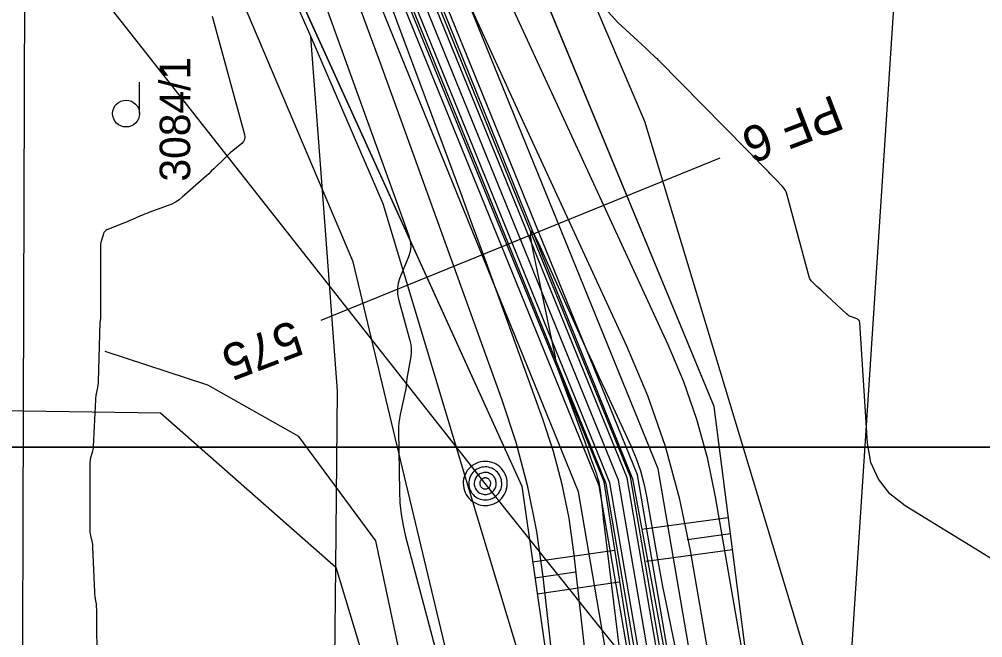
# Model space of a CAD drawing. Extents: x -534410 to -534262, y -1190162 to -1189584.
# Drawn here: x -534342.11 to -534315.26, y -1190009.78 to -1189992.54 of the extents above; entities that cross this region are included whole.
import ezdxf

# ---------------------------------------------------------------- set-up
doc = ezdxf.new("R2010")
doc.units = 0
for name, color, linetype in [('07_ELEKTRO', 7, 'Continuous'), ('30', 7, 'Continuous'), ('31', 7, 'Continuous'), ('_linie', 7, 'Continuous'), ('_N_osa', 7, 'Continuous'), ('_N_tenká', 7, 'Continuous'), ('_N_tenká_velmi', 7, 'Continuous'), ('_N_text', 7, 'Continuous'), ('_přístup', 7, 'Continuous'), ('_rámeček', 7, 'Continuous'), ('_tenka', 7, 'Continuous'), ('_velmi_tenka', 7, 'Continuous'), ('Default', 7, 'Continuous'), ('Hranice parcel', 7, 'Continuous'), ('Parcelní čísla', 7, 'Continuous'), ('Vrstva 12', 7, 'Continuous'), ('Vrstva 15', 7, 'Continuous'), ('Vrstva 2', 7, 'Continuous'), ('Značky kultur', 7, 'Continuous')]:
    doc.layers.add(name, color=color, linetype=linetype)

# ---------------------------------------------------------------- blocks, each defined once
blk = doc.blocks.new('VN460')
at = {"layer": 'Vrstva 2'}
for points in [[(0.1229, -0.0001), (0.1221, 0.0128), (0.1201, 0.0255), (0.1168, 0.0379), (0.1122, 0.0499), (0.1064, 0.0613), (0.0994, 0.0722), (0.0913, 0.0822), (0.0822, 0.0912), (0.0722, 0.0993), (0.0614, 0.1063), (0.05, 0.1122), (0.0379, 0.1168), (0.0256, 0.1201), (0.0128, 0.1221), (0, 0.1228), (-0.0128, 0.1221), (-0.0256, 0.1201), (-0.0379, 0.1168), (-0.05, 0.1122), (-0.0614, 0.1063), (-0.0722, 0.0993), (-0.0822, 0.0912), (-0.0913, 0.0822), (-0.0994, 0.0722), (-0.1064, 0.0613), (-0.1122, 0.0499), (-0.1168, 0.0379), (-0.1202, 0.0255), (-0.1221, 0.0128), (-0.1229, -0.0001), (-0.1221, -0.0129), (-0.1202, -0.0256), (-0.1168, -0.038), (-0.1122, -0.05), (-0.1064, -0.0615), (-0.0994, -0.0723), (-0.0913, -0.0823), (-0.0822, -0.0914), (-0.0722, -0.0995), (-0.0614, -0.1064), (-0.05, -0.1123), (-0.0379, -0.1169), (-0.0256, -0.1202), (-0.0128, -0.1223), (0, -0.1229), (0.0128, -0.1222), (0.0256, -0.1202), (0.0379, -0.1169), (0.05, -0.1123), (0.0614, -0.1064), (0.0722, -0.0995), (0.0822, -0.0914), (0.0913, -0.0823), (0.0994, -0.0723), (0.1064, -0.0615), (0.1122, -0.05), (0.1168, -0.038), (0.1201, -0.0256), (0.1221, -0.0129), (0.1229, -0.0001)], [(0.0922, -0.0001), (0.0916, 0.0096), (0.0901, 0.0191), (0.0876, 0.0284), (0.0842, 0.0374), (0.0798, 0.046), (0.0745, 0.0541), (0.0685, 0.0616), (0.0616, 0.0684), (0.0541, 0.0745), (0.046, 0.0797), (0.0375, 0.0841), (0.0285, 0.0876), (0.0191, 0.0901), (0.0096, 0.0916), (0, 0.0921), (-0.0096, 0.0916), (-0.0191, 0.0901), (-0.0285, 0.0876), (-0.0375, 0.0841), (-0.0461, 0.0797), (-0.0542, 0.0745), (-0.0617, 0.0684), (-0.0685, 0.0616), (-0.0745, 0.0541), (-0.0798, 0.046), (-0.0842, 0.0374), (-0.0876, 0.0284), (-0.0901, 0.0191), (-0.0916, 0.0096), (-0.0921, -0.0001), (-0.0916, -0.0097), (-0.0901, -0.0192), (-0.0876, -0.0285), (-0.0842, -0.0375), (-0.0798, -0.0461), (-0.0745, -0.0542), (-0.0685, -0.0617), (-0.0616, -0.0685), (-0.0542, -0.0746), (-0.0461, -0.0798), (-0.0375, -0.0842), (-0.0285, -0.0877), (-0.0191, -0.0902), (-0.0096, -0.0917), (0, -0.0922), (0.0096, -0.0917), (0.0191, -0.0902), (0.0285, -0.0877), (0.0375, -0.0842), (0.046, -0.0798), (0.0541, -0.0746), (0.0616, -0.0685), (0.0685, -0.0617), (0.0745, -0.0542), (0.0798, -0.0461), (0.0842, -0.0375), (0.0876, -0.0285), (0.0901, -0.0192), (0.0916, -0.0097), (0.0922, -0.0001)], [(0.0614, -0.0001), (0.0611, 0.0063), (0.0601, 0.0127), (0.0584, 0.0189), (0.0561, 0.0249), (0.0532, 0.0306), (0.0497, 0.036), (0.0456, 0.041), (0.0411, 0.0456), (0.0361, 0.0496), (0.0307, 0.0531), (0.025, 0.056), (0.019, 0.0584), (0.0128, 0.06), (0.0064, 0.061), (0, 0.0613), (-0.0064, 0.061), (-0.0128, 0.06), (-0.019, 0.0584), (-0.025, 0.056), (-0.0307, 0.0531), (-0.0361, 0.0496), (-0.0411, 0.0456), (-0.0457, 0.041), (-0.0497, 0.036), (-0.0532, 0.0306), (-0.0561, 0.0249), (-0.0584, 0.0189), (-0.0601, 0.0127), (-0.0611, 0.0063), (-0.0614, -0.0001), (-0.0611, -0.0065), (-0.0601, -0.0128), (-0.0584, -0.0191), (-0.0561, -0.025), (-0.0532, -0.0308), (-0.0497, -0.0361), (-0.0457, -0.0411), (-0.0411, -0.0457), (-0.0361, -0.0498), (-0.0307, -0.0532), (-0.025, -0.0561), (-0.019, -0.0585), (-0.0128, -0.0601), (-0.0064, -0.0611), (0, -0.0615), (0.0064, -0.0611), (0.0128, -0.0601), (0.019, -0.0585), (0.025, -0.0561), (0.0307, -0.0532), (0.0361, -0.0498), (0.0411, -0.0457), (0.0456, -0.0411), (0.0497, -0.0361), (0.0532, -0.0308), (0.0561, -0.025), (0.0584, -0.0191), (0.0601, -0.0128), (0.0611, -0.0065), (0.0614, -0.0001)], [(0.0307, -0.0001), (0.0306, 0.0031), (0.03, 0.0063), (0.0292, 0.0094), (0.0281, 0.0124), (0.0266, 0.0153), (0.0248, 0.018), (0.0228, 0.0205), (0.0206, 0.0228), (0.0181, 0.0248), (0.0153, 0.0265), (0.0125, 0.028), (0.0095, 0.0291), (0.0064, 0.03), (0.0032, 0.0305), (0, 0.0306), (-0.0032, 0.0305), (-0.0064, 0.03), (-0.0095, 0.0291), (-0.0125, 0.028), (-0.0154, 0.0265), (-0.0181, 0.0248), (-0.0206, 0.0228), (-0.0228, 0.0205), (-0.0248, 0.018), (-0.0266, 0.0153), (-0.0281, 0.0124), (-0.0292, 0.0094), (-0.03, 0.0063), (-0.0306, 0.0031), (-0.0307, -0.0001), (-0.0306, -0.0033), (-0.03, -0.0065), (-0.0292, -0.0095), (-0.0281, -0.0126), (-0.0266, -0.0154), (-0.0248, -0.0181), (-0.0228, -0.0206), (-0.0206, -0.0229), (-0.0181, -0.0249), (-0.0154, -0.0267), (-0.0125, -0.0281), (-0.0095, -0.0292), (-0.0064, -0.0301), (-0.0032, -0.0306), (0, -0.0308), (0.0032, -0.0306), (0.0064, -0.0301), (0.0095, -0.0292), (0.0125, -0.0281), (0.0153, -0.0267), (0.0181, -0.0249), (0.0206, -0.0229), (0.0228, -0.0206), (0.0248, -0.0181), (0.0266, -0.0154), (0.0281, -0.0126), (0.0292, -0.0095), (0.03, -0.0065), (0.0306, -0.0033), (0.0307, -0.0001)]]:
    blk.add_lwpolyline(points, dxfattribs=at)

msp = doc.modelspace()

# ---------------------------------------------------------------- linework, layer by layer
at = {"layer": '07_ELEKTRO'}
msp.add_lwpolyline([(-534329.31, -1190087.46), (-534329.03, -1190079.95), (-534329.01, -1190078.66), (-534328.95, -1190069.47), (-534328.91, -1190061.75), (-534328.68, -1190054.09), (-534328.55, -1190046.44), (-534328.261, -1190025.497), (-534332.174, -1190007.081), (-534334.321, -1190004.167), (-534336.852, -1190002.737), (-534339.713, -1190001.803)], dxfattribs=at)
at = {"layer": '30'}
for points in [[(-534330.583, -1189987.403), (-534324.037, -1190001.603), (-534323.602, -1190002.632), (-534323.237, -1190003.683), (-534322.942, -1190004.756), (-534322.716, -1190005.85), (-534321.8, -1190011.157)], [(-534326.785, -1190014.533), (-534327.509, -1190008.078), (-534327.688, -1190006.814), (-534327.941, -1190005.568), (-534328.266, -1190004.338), (-534328.664, -1190003.126), (-534331.461, -1189995.381), (-534332.074, -1189993.689), (-534332.691, -1189991.999)], [(-534336.734, -1189992.452), (-534335.832, -1189995.749), (-534335.821, -1189995.823), (-534335.831, -1189995.889), (-534335.862, -1189995.95), (-534335.913, -1189996.003), (-534336.159, -1189996.205), (-534336.22, -1189996.256), (-534336.279, -1189996.308), (-534336.338, -1189996.362), (-534336.395, -1189996.417), (-534336.69, -1189996.71), (-534336.759, -1189996.777), (-534336.828, -1189996.843), (-534336.898, -1189996.907), (-534336.97, -1189996.971), (-534337.569, -1189997.502), (-534337.659, -1189997.574), (-534337.754, -1189997.637), (-534337.855, -1189997.69), (-534337.962, -1189997.734), (-534338.503, -1189997.928), (-534338.56, -1189997.949), (-534338.617, -1189997.971), (-534338.674, -1189997.995), (-534338.73, -1189998.019), (-534338.954, -1189998.118), (-534339.01, -1189998.142), (-534339.066, -1189998.166), (-534339.122, -1189998.19), (-534339.179, -1189998.213), (-534339.668, -1189998.411), (-534339.702, -1189998.429), (-534339.73, -1189998.453), (-534339.751, -1189998.483), (-534339.766, -1189998.519), (-534339.829, -1189998.73), (-534339.832, -1189998.741), (-534339.835, -1189998.752), (-534339.837, -1189998.764), (-534339.839, -1189998.775), (-534339.845, -1189998.821), (-534339.846, -1189998.833), (-534339.847, -1189998.845), (-534339.848, -1189998.856), (-534339.848, -1189998.868), (-534339.848, -1190000.815), (-534339.848, -1190000.83), (-534339.849, -1190000.844), (-534339.85, -1190000.859), (-534339.851, -1190000.874), (-534339.858, -1190000.934), (-534339.86, -1190000.948), (-534339.861, -1190000.963), (-534339.862, -1190000.978), (-534339.863, -1190000.993), (-534339.912, -1190002.632), (-534339.913, -1190002.653), (-534339.914, -1190002.674), (-534339.916, -1190002.696), (-534339.919, -1190002.717), (-534339.932, -1190002.802), (-534339.935, -1190002.823), (-534339.938, -1190002.844), (-534339.942, -1190002.866), (-534339.946, -1190002.887), (-534339.973, -1190003.026), (-534339.979, -1190003.056), (-534339.983, -1190003.087), (-534339.986, -1190003.118), (-534339.988, -1190003.148), (-534340.052, -1190004.45), (-534340.055, -1190004.491), (-534340.06, -1190004.531), (-534340.068, -1190004.571), (-534340.078, -1190004.61), (-534340.123, -1190004.766), (-534340.132, -1190004.806), (-534340.139, -1190004.845), (-534340.144, -1190004.885), (-534340.145, -1190004.926), (-534340.147, -1190005.148), (-534340.147, -1190005.198), (-534340.147, -1190005.249), (-534340.147, -1190005.299), (-534340.147, -1190005.35), (-534340.147, -1190006.339), (-534340.147, -1190006.39), (-534340.147, -1190006.44), (-534340.148, -1190006.491), (-534340.148, -1190006.541), (-534340.149, -1190006.76), (-534340.148, -1190006.802), (-534340.144, -1190006.844), (-534340.138, -1190006.885), (-534340.13, -1190006.926), (-534340.09, -1190007.09), (-534340.081, -1190007.131), (-534340.074, -1190007.172), (-534340.07, -1190007.214), (-534340.067, -1190007.256), (-534340.016, -1190008.506), (-534340.014, -1190008.541), (-534340.011, -1190008.575), (-534340.006, -1190008.608), (-534340.001, -1190008.642), (-534339.975, -1190008.792), (-534339.971, -1190008.818), (-534339.967, -1190008.845), (-534339.965, -1190008.871), (-534339.964, -1190008.898), (-534339.96, -1190009.005), (-534339.959, -1190009.032), (-534339.958, -1190009.059), (-534339.958, -1190009.086), (-534339.957, -1190009.113), (-534339.946, -1190010.519)], [(-534324.401, -1190018.116), (-534325.773, -1190006.894), (-534325.791, -1190006.749), (-534325.808, -1190006.603), (-534325.825, -1190006.457), (-534325.842, -1190006.312), (-534325.914, -1190005.671), (-534325.93, -1190005.555), (-534325.953, -1190005.44), (-534325.983, -1190005.327), (-534326.02, -1190005.215), (-534326.18, -1190004.773), (-534326.22, -1190004.662), (-534326.26, -1190004.551), (-534326.301, -1190004.441), (-534326.342, -1190004.331), (-534327.097, -1190002.3), (-534327.11, -1190002.262), (-534327.121, -1190002.223), (-534327.13, -1190002.184), (-534327.138, -1190002.144), (-534327.164, -1190001.983), (-534327.171, -1190001.943), (-534327.178, -1190001.903), (-534327.186, -1190001.863), (-534327.194, -1190001.823), (-534327.798, -1189998.945), (-534327.863, -1189998.571), (-534327.85, -1189998.436), (-534327.76, -1189998.538), (-534327.592, -1189998.878), (-534326.468, -1190001.378), (-534326.299, -1190001.753), (-534326.13, -1190002.127), (-534325.959, -1190002.501), (-534325.787, -1190002.874), (-534325.06, -1190004.451), (-534324.919, -1190004.786), (-534324.8, -1190005.128), (-534324.704, -1190005.477), (-534324.631, -1190005.833), (-534324.382, -1190007.272), (-534324.319, -1190007.631), (-534324.253, -1190007.99), (-534324.183, -1190008.348), (-534324.111, -1190008.706), (-534322.204, -1190017.993)]]:
    msp.add_lwpolyline(points, dxfattribs=at)
at = {"layer": '31'}
for points in [[(-534325.805, -1190043.543), (-534325.051, -1190023.305), (-534325.036, -1190022.469), (-534325.055, -1190021.635), (-534325.106, -1190020.801), (-534325.192, -1190019.969), (-534325.598, -1190016.645), (-534325.699, -1190015.814), (-534325.797, -1190014.982), (-534325.894, -1190014.15), (-534325.988, -1190013.318), (-534326.654, -1190007.39), (-534326.788, -1190006.444), (-534326.977, -1190005.511), (-534327.22, -1190004.59), (-534327.518, -1190003.682), (-534328.82, -1190000.077), (-534329.147, -1189999.176), (-534329.476, -1189998.275), (-534329.807, -1189997.376), (-534330.139, -1189996.477), (-534336.286, -1189979.943)], [(-534334.815, -1189980.466), (-534330.995, -1189988.966), (-534330.298, -1189990.512), (-534329.597, -1189992.056), (-534328.893, -1189993.598), (-534328.185, -1189995.139), (-534325.187, -1190001.643), (-534324.603, -1190003.024), (-534324.113, -1190004.435), (-534323.717, -1190005.875), (-534323.414, -1190007.344), (-534322.095, -1190014.986), (-534321.984, -1190015.614), (-534321.868, -1190016.242), (-534321.747, -1190016.868), (-534321.621, -1190017.494), (-534321.51, -1190018.033)], [(-534334.708, -1189989.006), (-534331.253, -1189998.572), (-534331.214, -1189998.72), (-534331.203, -1189998.868), (-534331.22, -1189999.015), (-534331.265, -1189999.161), (-534331.503, -1189999.746), (-534331.55, -1189999.893), (-534331.571, -1190000.041), (-534331.568, -1190000.191), (-534331.539, -1190000.342), (-534331.224, -1190001.494), (-534331.2, -1190001.605), (-534331.188, -1190001.715), (-534331.189, -1190001.827), (-534331.203, -1190001.939), (-534331.31, -1190002.554), (-534331.314, -1190002.583), (-534331.318, -1190002.613), (-534331.322, -1190002.642), (-534331.324, -1190002.672), (-534331.337, -1190002.845), (-534331.338, -1190002.851), (-534331.339, -1190002.856), (-534331.345, -1190002.87), (-534331.347, -1190002.876), (-534331.347, -1190002.879), (-534331.494, -1190003.555), (-534331.516, -1190003.669), (-534331.53, -1190003.784), (-534331.539, -1190003.899), (-534331.54, -1190004.015), (-534331.516, -1190005.699), (-534331.502, -1190006.017), (-534331.469, -1190006.332), (-534331.416, -1190006.645), (-534331.344, -1190006.955), (-534330.495, -1190010.169)], [(-534311.946, -1190009.465), (-534317.42, -1190006.098), (-534317.852, -1190005.764), (-534318.17, -1190005.362), (-534318.376, -1190004.892), (-534318.47, -1190004.353), (-534318.684, -1190001.002), (-534318.691, -1190000.965), (-534318.707, -1190000.934), (-534318.732, -1190000.91), (-534318.766, -1190000.893), (-534318.919, -1190000.837), (-534318.956, -1190000.821), (-534318.991, -1190000.802), (-534319.024, -1190000.779), (-534319.055, -1190000.753), (-534319.731, -1190000.119), (-534319.74, -1190000.111), (-534319.748, -1190000.104), (-534319.757, -1190000.096), (-534319.766, -1190000.088), (-534319.836, -1190000.029), (-534319.88, -1189999.991), (-534319.89, -1189999.982), (-534319.9, -1189999.973), (-534319.91, -1189999.964), (-534319.919, -1189999.954), (-534320.038, -1189999.829), (-534320.06, -1189999.804), (-534320.077, -1189999.776), (-534320.091, -1189999.747), (-534320.102, -1189999.716), (-534320.707, -1189997.445), (-534320.729, -1189997.378), (-534320.759, -1189997.316), (-534320.796, -1189997.257), (-534320.841, -1189997.204), (-534321.037, -1189996.997), (-534321.086, -1189996.946), (-534321.136, -1189996.894), (-534321.185, -1189996.843), (-534321.235, -1189996.792), (-534324.301, -1189993.675), (-534324.329, -1189993.646), (-534324.358, -1189993.619), (-534324.387, -1189993.591), (-534324.417, -1189993.564), (-534324.536, -1189993.456), (-534324.566, -1189993.429), (-534324.595, -1189993.402), (-534324.625, -1189993.375), (-534324.654, -1189993.348), (-534325.431, -1189992.628), (-534325.433, -1189992.626), (-534327.845, -1189989.955)]]:
    msp.add_lwpolyline(points, dxfattribs=at)
at = {"layer": '_linie'}
for points in [[(-534351.8, -1189951.99), (-534346.88, -1189964.25), (-534328.11, -1190005.55), (-534325.796, -1190021.686), (-534325.86, -1190050.97), (-534326.22, -1190078.56), (-534326.79, -1190120.4), (-534329.12, -1190134.93), (-534323.49, -1190133.89), (-534321.38, -1190121.46), (-534319.59, -1190053.22), (-534320.45, -1190021.195), (-534322.75, -1190003.33), (-534340.65, -1189960.04), (-534344.52, -1189948.89)], [(-534347.45, -1189950.137), (-534345.54, -1189954.54), (-534325.02, -1190005.35), (-534322.054, -1190021.393), (-534321.72, -1190051.56), (-534322.31, -1190078.15), (-534323.81, -1190120.37), (-534326.521, -1190134.45)], [(-534328.194, -1190134.759), (-534324.85, -1190120.45), (-534324.6, -1190078.17), (-534323.54, -1190051.92), (-534323.273, -1190021.516), (-534325.81, -1190005.43), (-534346.66, -1189954.59), (-534348.342, -1189950.518)]]:
    msp.add_lwpolyline(points, dxfattribs=at)
at = {"layer": '_N_osa'}
msp.add_lwpolyline([(-534327.357, -1190134.604), (-534324.33, -1190120.41), (-534323.455, -1190078.16), (-534322.63, -1190051.74), (-534322.663, -1190021.455), (-534325.415, -1190005.39), (-534346.1, -1189954.565), (-534347.892, -1189950.326)], dxfattribs=at)
at = {"layer": '_N_tenká'}
for points in [[(-534326.133, -1190134.378), (-534323.183, -1190120.543), (-534322.305, -1190078.19), (-534321.48, -1190051.757), (-534321.513, -1190021.356), (-534324.303, -1190005.072), (-534345.038, -1189954.124), (-534346.832, -1189949.878)], [(-534327.091, -1190134.555), (-534324.081, -1190120.439), (-534323.205, -1190078.166), (-534322.38, -1190051.744), (-534322.413, -1190021.433), (-534325.173, -1190005.321), (-534345.869, -1189954.469), (-534347.661, -1189950.228)], [(-534327.623, -1190134.654), (-534324.579, -1190120.381), (-534323.705, -1190078.154), (-534322.88, -1190051.736), (-534322.913, -1190021.476), (-534325.657, -1190005.459), (-534346.331, -1189954.661), (-534348.122, -1189950.423)], [(-534328.581, -1190134.83), (-534325.477, -1190120.277), (-534324.605, -1190078.13), (-534323.78, -1190051.723), (-534323.813, -1190021.553), (-534326.527, -1190005.708), (-534347.162, -1189955.006), (-534348.951, -1189950.773)]]:
    msp.add_lwpolyline(points, dxfattribs=at)
at = {"layer": '_N_tenká_velmi'}
for points in [[(-534326.772, -1190134.496), (-534323.781, -1190120.474), (-534322.905, -1190078.174), (-534322.08, -1190051.748), (-534322.113, -1190021.407), (-534324.883, -1190005.238), (-534345.592, -1189954.354), (-534347.385, -1189950.112)], [(-534326.985, -1190134.536), (-534323.981, -1190120.45), (-534323.105, -1190078.169), (-534322.28, -1190051.745), (-534322.313, -1190021.425), (-534325.076, -1190005.293), (-534345.777, -1189954.431), (-534347.569, -1189950.189)], [(-534327.943, -1190134.713), (-534324.879, -1190120.346), (-534324.005, -1190078.146), (-534323.18, -1190051.732), (-534323.213, -1190021.502), (-534325.947, -1190005.542), (-534346.608, -1189954.776), (-534348.398, -1189950.54)], [(-534327.73, -1190134.673), (-534324.679, -1190120.37), (-534323.805, -1190078.151), (-534322.98, -1190051.735), (-534323.013, -1190021.485), (-534325.754, -1190005.487), (-534346.423, -1189954.699), (-534348.214, -1189950.462)]]:
    msp.add_lwpolyline(points, dxfattribs=at)
at = {"layer": '_N_text'}
msp.add_lwpolyline([(-534322.59, -1189996.415), (-534333.705, -1190000.939)], dxfattribs=at)
at = {"layer": '_přístup'}
msp.add_lwpolyline([(-534330.552, -1190135.191), (-534328.648, -1190119.819), (-534326.845, -1190024.247), (-534332.805, -1189999.297), (-534354.454, -1189948.317)], dxfattribs=at)
at = {"layer": '_rámeček'}
for points in [[(-534410.126, -1189899.47), (-534261.626, -1189899.47), (-534261.626, -1190004.47), (-534410.126, -1190004.47)], [(-534410.126, -1190004.47), (-534261.626, -1190004.47), (-534261.626, -1190109.47), (-534410.126, -1190109.47)]]:
    msp.add_lwpolyline(points, close=True, dxfattribs=at)
at = {"layer": '_tenka'}
for points in [[(-534351.8, -1189951.99), (-534346.88, -1189964.25), (-534328.11, -1190005.55), (-534325.796, -1190021.686), (-534325.86, -1190050.97), (-534326.22, -1190078.56), (-534326.79, -1190120.4), (-534329.12, -1190134.93), (-534323.49, -1190133.89), (-534321.38, -1190121.46), (-534319.59, -1190053.22), (-534320.45, -1190021.195), (-534322.75, -1190003.33), (-534340.65, -1189960.04), (-534344.52, -1189948.89)], [(-534327.55, -1190134.64), (-534323.49, -1190133.89), (-534321.38, -1190121.46), (-534319.59, -1190053.22), (-534320.45, -1190021.195), (-534322.75, -1190003.33), (-534340.65, -1189960.04), (-534344.52, -1189948.89)], [(-534347.45, -1189950.137), (-534345.54, -1189954.54), (-534325.02, -1190005.35), (-534322.054, -1190021.393), (-534321.72, -1190051.56), (-534322.31, -1190078.15), (-534323.81, -1190120.37), (-534326.521, -1190134.45)], [(-534347.45, -1189950.137), (-534345.54, -1189954.54), (-534325.02, -1190005.35), (-534322.054, -1190021.393), (-534321.72, -1190051.56), (-534322.31, -1190078.15), (-534323.81, -1190120.37), (-534326.521, -1190134.45)], [(-534328.194, -1190134.759), (-534324.85, -1190120.45), (-534324.6, -1190078.17), (-534323.54, -1190051.92), (-534323.273, -1190021.516), (-534325.81, -1190005.43), (-534346.66, -1189954.59), (-534348.342, -1189950.518)], [(-534328.194, -1190134.759), (-534324.85, -1190120.45), (-534324.6, -1190078.17), (-534323.54, -1190051.92), (-534323.273, -1190021.516), (-534325.81, -1190005.43), (-534346.66, -1189954.59), (-534348.342, -1189950.518)], [(-534351.8, -1189951.99), (-534346.88, -1189964.25), (-534328.11, -1190005.55), (-534325.796, -1190021.686), (-534325.86, -1190050.97), (-534326.22, -1190078.56), (-534326.79, -1190120.4), (-534329.12, -1190134.93), (-534327.55, -1190134.64)]]:
    msp.add_lwpolyline(points, dxfattribs=at)
at = {"layer": '_velmi_tenka'}
for p, q in [((-534322.352, -1190006.44), (-534324.763, -1190006.763)), ((-534322.292, -1190006.886), (-534323.497, -1190007.047)), ((-534327.807, -1190007.664), (-534325.526, -1190007.333)), ((-534322.232, -1190007.332), (-534324.643, -1190007.655)), ((-534327.743, -1190008.11), (-534326.602, -1190007.944)), ((-534327.678, -1190008.555), (-534325.396, -1190008.224))]:
    msp.add_line(p, q, dxfattribs=at)
at = {"layer": 'Default'}
for p, q in [((-534322.75, -1190003.33), (-534340.65, -1189960.04)), ((-534346.88, -1189964.25), (-534328.11, -1190005.55))]:
    msp.add_line(p, q, dxfattribs=at)
for points in [[(-534319.59, -1190053.22), (-534320.45, -1190021.195), (-534322.75, -1190003.33)], [(-534328.11, -1190005.55), (-534325.796, -1190021.686), (-534325.86, -1190050.97)]]:
    msp.add_lwpolyline(points, dxfattribs=at)
at = {"layer": 'Hranice parcel'}
for p, q in [((-534319.25, -1190015.38), (-534314.72, -1189945.99)), ((-534341.9, -1189974.75), (-534333.99, -1189993.03)), ((-534365.84, -1190003.05), (-534341.99, -1190003.45)), ((-534333.46, -1190024.63), (-534333.29, -1190007.81)), ((-534333.29, -1190007.81), (-534328.17, -1190024.72))]:
    msp.add_line(p, q, dxfattribs=at)
for points in [[(-534341.99, -1190003.45), (-534341.91, -1189977.12), (-534341.9, -1189974.75)], [(-534319.25, -1190015.38), (-534319.67, -1190011.96), (-534324.68, -1189995.39), (-534326.36, -1189991.44)], [(-534333.29, -1190007.81), (-534333.24, -1190002.9), (-534333.62, -1189997.8), (-534333.99, -1189993.03)], [(-534333.99, -1189993.03), (-534331.98, -1189997.67), (-534327.34, -1190013.08), (-534325.48, -1190021.81), (-534326.93, -1190073), (-534328.13, -1190128.3), (-534328.71, -1190131.86)], [(-534342.06, -1190024.47), (-534342.05, -1190022.37), (-534341.99, -1190003.45)], [(-534341.99, -1190003.45), (-534338.18, -1190003.51), (-534333.29, -1190007.81)]]:
    msp.add_lwpolyline(points, dxfattribs=at)
at = {"layer": 'Vrstva 12'}
msp.add_lwpolyline([(-534315.834, -1190022.126), (-534329.125, -1190005.478), (-534340.302, -1189991.272)], dxfattribs=at)
at = {"layer": 'Značky kultur'}
msp.add_line((-534338.758, -1189995.166), (-534338.758, -1189994.291), dxfattribs=at)
msp.add_circle((-534339.134, -1189995.166), 0.375, dxfattribs=at)

# ---------------------------------------------------------------- block references
at = {"layer": 'Vrstva 15', "xscale": 5.000000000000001, "yscale": 5.000000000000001, "rotation": -53.49649728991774}
msp.add_blockref('VN460', (-534329.125, -1190005.477), dxfattribs=at)

# ---------------------------------------------------------------- texts
at = {"layer": '_N_text'}
for s, rotation, p in [('PF 6', 200.9666, (-534319.416, -1189994.63)), ('575', 200.9191, (-534334.468, -1190000.907))]:
    msp.add_text(s, height=1, rotation=rotation, dxfattribs=at).set_placement(p)
at = {"layer": 'Parcelní čísla'}
msp.add_text('3084/1', height=0.85, rotation=90, dxfattribs=at).set_placement((-534337.348, -1189997.063))

doc.saveas('drawing.dxf')
